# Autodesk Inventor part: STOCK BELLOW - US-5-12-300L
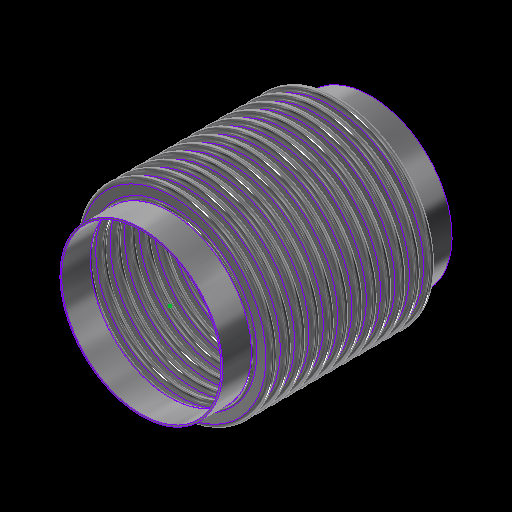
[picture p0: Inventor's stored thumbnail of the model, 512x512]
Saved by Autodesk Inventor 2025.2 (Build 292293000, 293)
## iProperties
Category: 22 GA (0.030 THICK)
RuleStatus: InUse
Created: 2024-01
Part Number: STOCK BELLOW - US-5-12-300L
Project: =STOCK BELLOWS: <Stock Number><SFILL>
Material: ASTM A240-304
Description: =STOCK BELLOWS: <Stock Number>, <SID_> I.D., <SOD_> O.D., <SPLY_> PLY, <Category>, <SNET_CONS> CONS.<PITCH_><STANGENT_> TANGENT<SFILL>
Document SubType Name: Sheet Metal
Designer: GS
Stock Number: U.S-5-12-300L
Surface Area: 4755.04 cm^2
Volume: 359.21 cm^3
Sheet Metal Rule: Default
Appearance: STAINLESS STEEL
Mass: 2894.25 g
Density: 8.05729 g/cm^3
THK: 0.036
ID: 3.500
OD: 4.250
CONS_: 2
PITCH: 0.500
TANGENT: 0.500
BELLOWS_UPSET: 0.000
d79: 1.000
d82: 1.000
d83: 26.000
d84: 24.000
d174: 8
d214: 8
STHK_: 0.030
SID_: 5.560
SOD_: 6.810
SPITCH_: 0.500
STANGENT__: 1.000
SBELLOWS_UPSET_: 0.000
SDIFF_TAN: 1.000
d252: 2
d275: 2
d287: 0.050
d289: 0.500
d290: 0.000
SOD_NECK: 5 11/16
PLY: 1
PSET: 4.178
PBAR: 1.035
COUNTER: 1.500
NET_TUBE: 3.071
CONS: 2
S_CONS: 0
NET_CONS: 2
ID_M: 88.90 mm
OD_M: 107.95 mm
THK_M: 0.91 mm
ID_U: 3.500 in
OD_U: 4.250 in
THK_U: 0.036 in
TANGENT2: 0.500
TAN_TO_TAN: 1.000 in
d80: 2.571
d81: 10
SID: 2.375
SCONS_: 12
SPITCH: 0.250
STANGENT_: 1.000
SBELLOWS_UPSET: 0.000
SNET_CONS: 12
SS_CONS: 0
SCONS: 8
d190: 8
d191: 1
d192: 1
d193: 8
d194: 0
SIZE: 5.00
PRESSURE: 300
d230: 8
STANGENT: 4.000
SPLY_: 2
d233: 8
d234: 0
d263: 2
d265: 1
d268: 2
d269: 0
d286: 2
d288: 1
d291: 2
d292: 0
SREROLL: 0.750
BLETP: 1.000 ul
PRES_Copy: 85
MATTABLE: 20 GA (0.036 THICK)
PART_NUMBER: U.S-5-12-300L
PITCH_: =, <SPITCH_> PITCH,
CFILL: .
SFILL: .
MESH: ,
COMP: 1.11
EXT: 0.56
LAT: 0.36
ANG: 573
ASR: 2144
LSR: 3418
ANSR: 179
PRES: 300
COMPM: 11.1
EXTM: 5.55
LATM: 3.60
ASRM: 375.479
PRESM: 20.684
LSRM: 598.594
ANSRM: 31.348
TEMPMIN: 20
TEMPMAX: 800
TEMPMINM: -7
TEMPMAXM: 427
WEIGHTM: 2.894
WEIGHT: 6.381
Author: GS
Keywords: 20 GA (0.036 THICK)
Comments: =STOCK BELLOW - <STOCK NUMBER>
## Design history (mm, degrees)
sketch "Sketch2"
  geometry: L1 (0, -177.245)-(0, 562.856) reference; L2 (45.364, 0)-(44.45, 0); L3 (48.082, -2.718)-(50.343, -2.718); L4 (48.082, -3.632)-(50.343, -3.632); L5 (50.343, -9.982)-(48.082, -9.982); L6 (50.343, -9.068)-(48.082, -9.068); L7 (45.364, -12.7)-(44.45, -12.7); L8 (48.082, 0)-(48.082, -12.7); L9 (50.343, -6.35)-(53.975, -6.35); L10 (44.45, 0)-(44.45, -12.7); L11 (20.376, 102.841)-(20.376, 101.926); L12 (58.262, 457.127)-(58.262, 349.177); L13 (58.262, 444.427)-(58.262, 336.477); L14 (93.133, -58.817)-(93.133, -71.517); L15 (118.746, -66.401)-(118.746, -66.401); L16 (50.343, -9.068)-(50.343, -9.982); L17 (48.082, -9.068)-(48.082, -9.982); L18 (48.082, -9.525)-(50.343, -9.525); L19 (53.975, 0)-(53.975, -12.7); L20 (-50.343, -9.068)-(-50.343, -9.982); L21 (-50.343, -2.718)-(-48.082, -2.718); L22 (-50.343, -3.632)-(-48.082, -3.632); L23 (-48.082, -9.068)-(-50.343, -9.068); L24 (-50.343, -9.525)-(-48.082, -9.525); L25 (-48.082, -9.982)-(-50.343, -9.982); L26 (-48.082, -9.068)-(-48.082, -9.982); L27 (-44.45, 0.653)-(-44.45, -12.047); L28 (-48.082, -6.35)-(-44.45, -6.35); L29 (-50.343, 0.653)-(-50.343, -12.7); L30 (-53.061, 0)-(-53.975, 0); L31 (-53.975, 0)-(-53.975, -12.7); L32 (-53.061, -12.7)-(-53.975, -12.7); A1 r 2.718 centre (48.082, 0) between (45.364, 0) and (48.082, -2.718); A2 r 3.632 centre (48.082, 0) between (44.45, 0) and (48.082, -3.632); A3 r 3.632 centre (50.343, -6.35) between (50.343, -9.982) and (50.343, -2.718); A4 r 2.718 centre (50.343, -6.35) between (50.343, -9.068) and (50.343, -3.632); A5 r 2.718 centre (48.082, -12.7) between (48.082, -9.982) and (45.364, -12.7); A6 r 3.632 centre (48.082, -12.7) between (48.082, -9.068) and (44.45, -12.7); A7 r 3.175 centre (50.343, -6.35) between (50.343, -9.525) and (53.518, -6.35); A8 r 3.175 centre (48.082, -12.7) between (48.082, -9.525) and (44.907, -12.7); A9 r 2.718 centre (-50.343, -12.7) between (-50.343, -9.982) and (-53.061, -12.7); A10 r 2.718 centre (-48.082, -6.35) between (-48.082, -9.068) and (-48.082, -3.632); A11 r 3.175 centre (-48.082, -6.35) between (-48.082, -9.525) and (-44.907, -6.35); A12 r 3.632 centre (-48.082, -6.35) between (-48.082, -9.982) and (-48.082, -2.718); A13 r 3.175 centre (-50.343, -12.7) between (-50.343, -9.525) and (-53.518, -12.7); A14 r 3.632 centre (-50.343, -12.7) between (-50.343, -9.068) and (-53.975, -12.7); A15 r 2.718 centre (-50.343, 0) between (-53.061, 0) and (-50.343, -2.718); A16 r 3.632 centre (-50.343, 0) between (-53.975, 0) and (-50.343, -3.632); 10 further points
  constraints: 62 end point, 38 point on circle, 20 tangent, 16 centre point, 12 parallel, 9 midpoint, 7 vertical, 6 coincident, 6 concentric, 6 point on line, 4 equal radius, 4 perpendicular, 3 horizontal, 1 collinear, 1 horizontal alignment, 10 other
  dimensions: "THK" = 0.9144 distance of L11.start L11.end; "ID" = 88.9 distance of L11.end point (20.376, 13.026); "OD" = 107.95 distance of L12.start L12.end; "PITCH" = 12.7 distance of L12.start L13.start; "TANGENT" = 12.7 distance of L14.start L14.end; "BELLOWS_UPSET" = 0 distance of L15.start L15.end; "d43" = 88.9 diameter of L10 L1 (= ID); "d44" = 107.95 diameter of L9.end L1 (= OD); "d45" = 0.9144 distance between parallel lines of L5 L6 (computed from THK, PLY); "d46" = 3.6322 radius of A3 (computed from PITCH, THK, PLY); "UPSET_PITCH" = 12.7 distance of L2.end L7.end (derived); "SIDEWALL_ANGLE" = 360 deg dimension on L3 L9 (derived); "CON_GAP" = 5.4356 distance of point (48.082, -9.068) point (48.082, -3.632) (derived); "TAN1" = 4.98728 dimension on A8 (derived); "TAN2" = 4.98728 dimension on A7 (derived); "LEG1" = 2.2606 distance of L18.start L18.end (derived); "d278" = 0.9144 distance between parallel lines of L25 L23 (derived); "d279" = 3.6322 radius of A12 (derived); "d280" = 12.7 distance of L30.end L31.end (derived); "d281" = 360 deg dimension on L21 L28 (derived); "d282" = 5.4356 distance of point (-50.343, -9.068) point (-50.343, -3.632) (derived); "d283" = 4.98728 dimension on A13 (derived); "d284" = 4.98728 dimension on A11 (derived); "d285" = 2.2606 distance of L24.start L24.end (derived); "d293" = 88.9 diameter of L27 L1 (derived); "d294" = 107.95 diameter of L31 L1 (derived)
  node "Sketch Rectangular Pattern1" dims "d31" = 25.4, "ID" = 88.9
  node "Sketch Rectangular Pattern2" dims "d39" = 25.4, "PITCH" = 12.7
revolve "CONS" stored, may be unused: angle "d48" = 90 deg
node "BELLOW MIDPLANE"
pattern_linear "Rectangular Pattern2" dims "d52" = 12.7 (= UPSET_PITCH)
sketch "Sketch5"
  geometry: C1 r 45.364 at (0, 0) reference; C2 r 44.45 at (0, 0) reference
extrude "TANGENT" new body sketch "Sketch5" distance "d53" = 12.7 (= TANGENT); taper "d54" = 0 deg
revolve "SAMETAN" stored, may be unused: angle "d65" = 90 deg
revolve "DIFFTAN" stored, may be unused: angle "d70" = 90 deg
sketch "Sketch9"
  geometry: L1 (53.319, 0)-(-53.319, 0) reference; L2 (0, -17.78)-(0, 17.78) reference; L3 (38.085, 0)-(-38.085, 0); L4 (38.085, -11.906)-(38.085, 11.906); L5 (25.385, -11.906)-(25.385, 11.906); L6 (13.15, 11.906)-(13.15, -11.906); L7 (-25.385, -11.906)-(-25.385, 11.906); L8 (-38.085, -11.906)-(-38.085, 11.906); L9 (37.291, -11.906)-(37.291, 11.906); L10 (38.085, -11.906)-(37.291, -11.906); L11 (38.085, 11.906)-(37.291, 11.906); L12 (13.546, 11.906)-(12.753, 11.906); L13 (12.753, 11.906)-(12.753, -11.906); L14 (12.753, -11.906)-(13.546, -11.906); L15 (13.546, -11.906)-(13.546, 11.906); L16 (-13.546, 11.906)-(-13.546, -11.906); L17 (-13.15, 11.906)-(-13.15, -11.906); L18 (-13.546, -11.906)-(-12.753, -11.906); L19 (-12.753, -11.906)-(-12.753, 11.906); L20 (-12.753, 11.906)-(-13.546, 11.906); L21 (-38.085, -11.906)-(-37.291, -11.906); L22 (-37.291, -11.906)-(-37.291, 11.906); L23 (-37.291, 11.906)-(-38.085, 11.906); L24 (-38.085, 11.906)-(-38.085, -11.906); L25 (38.085, -0.397)-(-38.085, -0.397); L26 (-38.085, -0.397)-(-38.085, 0.397); L27 (-38.085, 0.397)-(38.085, 0.397); L28 (38.085, 0.397)-(38.085, -0.397); L29 (-38.085, 11.906)-(38.085, 11.906); L30 (38.085, 11.906)-(38.085, 12.7); L31 (38.085, 12.7)-(-38.085, 12.7); L32 (-38.085, 12.7)-(-38.085, 11.906); L33 (38.085, -11.906)-(-38.085, -11.906); L34 (-38.085, -11.906)-(-38.085, -12.7); L35 (-38.085, -12.7)-(38.085, -12.7); L36 (38.085, -12.7)-(38.085, -11.906); 30 further points
  constraints: 68 end point, 13 midpoint, 13 parallel, 8 horizontal, 7 perpendicular, 6 equal length, 3 point on line, 2 vertical, 14 other
  dimensions: "d115" = 23.8125 distance of L4.start L4.end (derived); "d116" = 12.7 distance between parallel lines of L4 L5 (derived); "d117" = 12.23516 distance between parallel lines of L5 L6 (derived); "d125" = 38.53427 distance between parallel lines of L7 L6 (derived); "d127" = 12.7 distance between parallel lines of L8 L7 (derived); "d128" = 24.93516 distance between parallel lines of L6 L4 (derived); "d130" = 76.16943 distance between parallel lines of L8 L4 (derived); "RULER_THK" = 0.79375 distance between parallel lines of L4 L9; "d135" = 0.79375 distance of L13.end L14.end (derived); "d138" = 26.29911 distance of L13.end L16.end (derived); "d143" = 0.79375 distance of L22.end L8.end (derived); "d144" = 0.79375 distance between parallel lines of L27 L25 (derived)
extrude "RULER" join sketch "Sketch9" distance "d149" = 0.79375 (derived); taper "d150" = 0 deg
extrude "BARS" join sketch "Sketch9" distance "d151" = 0.79375 (derived); taper "d152" = 0 deg
pattern_linear "Rectangular Pattern4" dims "d155" = 26.29911 (derived)
sketch "Sketch13"
  geometry: L1 (93.149, -52.467)-(93.149, -77.867); L2 (72.136, 0)-(70.612, 0); L3 (72.136, -12.7)-(70.612, -12.7); L4 (82.55, -10.287)-(74.549, -10.287); L5 (82.55, -8.763)-(74.549, -8.763); L6 (82.55, -6.35)-(86.487, -6.35); L7 (74.549, -2.413)-(82.55, -2.413); L8 (74.549, 0)-(74.549, -12.7); L9 (70.612, 0)-(70.612, -12.7); L10 (58.254, -323.457)-(58.254, -496.431); L11 (58.254, -336.157)-(58.254, -509.131); L12 (58.254, -361.557)-(58.254, -534.531); L13 (58.254, -374.257)-(58.254, -547.231); L14 (58.254, -386.957)-(58.254, -559.931); L15 (58.254, -399.657)-(58.254, -572.631); L16 (58.254, -412.357)-(58.254, -585.331); L17 (58.254, -348.857)-(58.254, -521.831); L18 (20.376, 102.688)-(20.376, 101.926); L19 (74.549, -3.937)-(82.55, -3.937); L20 (0, -722.935)-(0, 240.292) reference; L21 (-23.752, 0)-(142.514, 0) reference; A1 r 2.413 centre (74.549, 0) between (72.136, 0) and (74.549, -2.413); A2 r 2.413 centre (74.549, -12.7) between (74.549, -10.287) and (72.136, -12.7); A3 r 3.937 centre (74.549, -12.7) between (74.549, -8.763) and (70.612, -12.7); A4 r 2.413 centre (82.55, -6.35) between (82.55, -8.763) and (82.55, -3.937); A5 r 3.937 centre (82.55, -6.35) between (82.55, -10.287) and (82.55, -2.413); A6 r 3.937 centre (74.549, 0) between (70.612, 0) and (74.549, -3.937); 6 further points; 1 other entity
  constraints: 38 end point, 15 point on circle, 9 tangent, 6 centre point, 6 parallel, 5 vertical alignment, 4 point on line, 4 vertical, 3 coincident, 3 concentric, 2 collinear, 2 equal radius, 1 horizontal, 1 perpendicular, 23 other
  dimensions: "SBELLOWS_UPSET_" = 0 distance of point (118.762, -66.401) point (118.762, -66.401); "STOTAL_THK_BELLOW__" = 1.524 distance between parallel lines of L4 L5 (derived); "d224" = 3.937 radius of A5 (derived); "d225" = 12.7 distance of L2.end L3.end (derived); "SSIDEWALL_ANGLE_" = 360 deg dimension on L7 L6 (derived); "SSCON_GAP_" = 4.826 distance of point (74.549, -8.763) point (74.549, -3.937) (derived); "d235" = 141.224 diameter of L9 L20 (derived); "d236" = 172.974 diameter of L6.end L20 (derived)
  node "Sketch Rectangular Pattern4" dims "d228" = 25.4
  node "Sketch Rectangular Pattern5" dims "d229" = 25.4
revolve "SBELLOW" stored, may be unused: angle "d197" = 90 deg
pattern_linear "Rectangular Pattern5" dims "d204" = 12.7 (derived)
revolve "STANGENT" stored, may be unused: angle "d240" = 90 deg
revolve "SSAMETAN" stored, may be unused: angle "d241" = 90 deg
revolve "SDIFFTAN" stored, may be unused: angle "d246" = 90 deg
revolve "INVCON" stored, may be unused: angle "d295" = 90 deg
pattern_linear "Rectangular Pattern6" dims "d298" = 12.7 (derived)
revolve "INVTANGENT" stored, may be unused: angle "d302" = 90 deg
revolve "INVSAMETAN" stored, may be unused: angle "d307" = 90 deg
revolve "INVDIFFTAN" stored, may be unused: angle "d312" = 90 deg
sketch "ID BELLOW MOUNT CALC"
  geometry: L1 (44.45, 0)-(38.1, 0); L2 (38.1, 0)-(38.1, 12.7); L3 (38.1, 12.7)-(44.45, 12.7); L4 (44.45, 12.7)-(44.45, 0); L5 (36.513, 12.7)-(35.598, 12.7); L6 (35.598, 12.7)-(35.598, 0); L7 (35.598, 0)-(36.513, 0); L8 (36.513, 0)-(36.513, 12.7); L9 (0, -2.54)-(0, 15.24) reference; L10 (-8.89, 0)-(53.34, 0) reference; 1 further point
  constraints: 16 end point, 5 parallel, 2 collinear, 2 horizontal, 2 perpendicular
  dimensions: "d314" = 12.7 distance of L5.end L6.end (derived); "d315" = 0.9144 distance of L5.start L5.end (derived); "IG" = 1.5875 distance between parallel lines of L2 L8; "PIPE_OD" = 88.9 diameter of L4 L9; "PIPE_WALL" = 6.35 distance of L2.end L3.end; "ID_MT_BELLOW" = 71.1962 diameter of L6 L9 (derived)
revolve "CFILL" stored, may be unused: angle "d320" = 90 deg
pattern_linear "Rectangular Pattern7" dims "d323" = 12.7 (derived)
revolve "SFILL" stored, may be unused: angle "d324" = 90 deg
pattern_linear "Rectangular Pattern8" dims "d327" = 12.7 (derived)
node "STOCK BELLOW MIDPLANE"
node "BELLOW"
sketch "Sketch6"
  geometry: L1 (-12.7, 45.364)-(0, 45.364); L2 (0, 45.364)-(0, 44.45); L3 (0, 44.45)-(-12.7, 44.45); L4 (-12.7, 44.45)-(-12.7, 45.364); L5 (10.16, 0)-(-60.96, 0) reference; L6 (-38.1, -89.422)-(-38.1, 153.44) reference; 1 further point
  constraints: 8 end point, 2 parallel, 1 horizontal, 1 perpendicular
  dimensions: "d61" = 12.7 distance of L2.end L3.end (derived); "d62" = 0.9144 distance of L1.end L2.end (derived); "d63" = 88.9 diameter of L3 L5 (derived); "d64" = 25.4 distance between parallel lines of L4 L6 (derived)
sketch "Sketch12"
  geometry: 1 further point
sketch "Sketch14"
  geometry: L1 (-25.4, 72.136)-(0, 72.136); L2 (0, 72.136)-(0, 70.612); L3 (0, 70.612)-(-25.4, 70.612); L4 (-25.4, 70.612)-(-25.4, 72.136); L5 (5.08, 0)-(-30.48, 0) reference; L6 (0, -14.427)-(0, 86.563) reference; 1 further point
  constraints: 8 end point, 2 parallel, 1 collinear, 1 horizontal, 1 perpendicular
  dimensions: "d237" = 1.524 distance of L3.end L1.start (derived); "d238" = 141.224 diameter of L3 L5 (derived); "d239" = 25.4 distance of L1.start L1.end (derived); "SOD_NECK" = 144.272 diameter of L1 L5 (derived)
sketch "Sketch15"
  geometry: L1 (-14.427, 0)-(86.563, 0) reference; L2 (70.612, -152.4)-(72.136, -152.4); L3 (72.136, -152.4)-(72.136, -177.8); L4 (72.136, -177.8)-(70.612, -177.8); L5 (70.612, -177.8)-(70.612, -152.4); L6 (0, -215.9)-(0, 50.8) reference; 1 further point
  constraints: 8 end point, 2 parallel, 1 horizontal, 1 perpendicular
  dimensions: "d205" = 25.4 distance of L4.end L2.start (derived); "d206" = 1.524 distance of L3.end L4.end (derived); "d207" = 141.224 diameter of L5 L6 (derived); "d208" = 152.4 distance between parallel lines of L1 L2 (derived)
node "TANGENT_"
node "SAME_TAN"
sketch "Sketch8"
  geometry: L1 (45.364, -25.4)-(44.45, -25.4); L2 (44.45, -25.4)-(44.45, -38.1); L3 (44.45, -38.1)-(45.364, -38.1); L4 (45.364, -38.1)-(45.364, -25.4); L5 (0, -48.26)-(0, 22.86) reference; L6 (-89.422, 0)-(153.44, 0) reference; 1 further point
  constraints: 8 end point, 2 parallel, 1 horizontal, 1 perpendicular
  dimensions: "d66" = 88.9 diameter of L2 L5 (derived); "TOTAL_THK_BELLOW" = 0.9144 distance of L2.end L3.end (derived); "d68" = 25.4 distance between parallel lines of L1 L6 (derived); "d69" = 12.7 distance of L1.end L2.end (derived)
node "DIFF_TAN"
node "Sketch Rectangular Pattern3" dims "d138" = 26.29911 (derived), "d141" = 25.4
node "SBELLOW_"
node "STANGENT_"
node "SSAME_TAN"
sketch "Sketch16"
  geometry: L1 (72.136, -152.4)-(70.612, -152.4); L2 (70.612, -152.4)-(70.612, -177.8); L3 (70.612, -177.8)-(72.136, -177.8); L4 (72.136, -177.8)-(72.136, -152.4); L5 (0, -215.9)-(0, 50.8) reference; L6 (-14.427, 0)-(86.563, 0) reference; 1 further point
  constraints: 8 end point, 2 parallel, 1 horizontal, 1 perpendicular
  dimensions: "SDIFF_TAN" = 25.4 distance of L3.end L1.start; "d243" = 1.524 distance of L2.end L3.end (derived); "d244" = 152.4 distance between parallel lines of L1 L6 (derived); "d245" = 141.224 diameter of L2 L5 (derived)
node "SDIFF_TAN"
body "Solid15"
sketch "Sketch17"
  geometry: L1 (53.975, 12.7)-(53.061, 12.7); L2 (53.061, 12.7)-(53.061, 0); L3 (53.061, 0)-(53.975, 0); L4 (53.975, 0)-(53.975, 12.7); L5 (0, -2.54)-(0, 15.24) reference; L6 (-10.795, 0)-(64.77, 0) reference; 2 further points
  constraints: 8 end point, 2 parallel, 1 horizontal, 1 midpoint, 1 perpendicular, 1 point on line
  dimensions: "INVTANGENT" = 12.7 distance of L3.end L1.start (derived); "d300" = 0.9144 distance of L1.start L1.end (derived); "d301" = 107.95 diameter of L4 L5 (derived)
body "Solid16"
sketch "Sketch18"
  geometry: L1 (53.975, -25.4)-(53.061, -25.4); L2 (53.061, -25.4)-(53.061, -38.1); L3 (53.061, -38.1)-(53.975, -38.1); L4 (53.975, -38.1)-(53.975, -25.4); L5 (-10.795, 0)-(64.77, 0) reference; L6 (0, -48.26)-(0, 22.86) reference; 1 further point
  constraints: 8 end point, 2 parallel, 1 horizontal, 1 perpendicular
  dimensions: "d303" = 25.4 distance between parallel lines of L1 L5 (derived); "d304" = 12.7 distance of L3.end L1.start (derived); "d305" = 0.9144 distance of L2.end L3.end (derived); "d306" = 107.95 diameter of L4 L6 (derived)
body "Solid17"
sketch "Sketch19"
  geometry: L1 (53.975, -25.4)-(53.061, -25.4); L2 (53.061, -25.4)-(53.061, -38.1); L3 (53.061, -38.1)-(53.975, -38.1); L4 (53.975, -38.1)-(53.975, -25.4); L5 (0, -48.26)-(0, 22.86) reference; L6 (-10.795, 0)-(64.77, 0) reference; 1 further point
  constraints: 8 end point, 2 parallel, 1 horizontal, 1 perpendicular
  dimensions: "d308" = 12.7 distance of L1.end L2.end (derived); "d309" = 107.95 diameter of L4 L5 (derived); "d310" = 0.9144 distance of L2.end L3.end (derived); "d311" = 25.4 distance between parallel lines of L1 L6 (derived)
body "Solid18"
body "Solid19"
body "Solid20"
other parameters: "BMPL" = -76.2, "PSET" = 106.1212 (computed from OD, THK, PLY) [user parameter], "PBAR" = 26.29911 (= 0.570796 x PITCH + OD - ID) [user parameter; used in 1 equation term], "COUNTER" = 15 [user parameter], "NET_TUBE" = 77.99823 (computed from CONS_, PBAR, TANGENT) [user parameter], "S_CONS" = 0 [user parameter; used in 1 equation term], "ID_M" = 88.9 (= ID) [user parameter], "OD_M" = 107.95 (= OD) [user parameter], "THK_M" = 0.9144 (= THK) [user parameter], "ID_U" = 88.9 (= ID) [user parameter], "OD_U" = 107.95 (= OD) [user parameter], "THK_U" = 0.9144 (= THK) [user parameter], "D_UNITS" = 0 [user parameter], "TANGENT2" = 12.7 [user parameter], "TAN_TO_TAN" = 25.4 [user parameter], "OD_NECK" = 90.7288 [user parameter], "d79" = 25.4, "d80" = 65.29823 [user parameter], "d82" = 25.4, "d83" = 660.4, "d84" = 609.6, "sa_0" = 4, "FRAME_THK" = 0.79375 [user parameter], "CON_FLAT" = 12.23516 [user parameter], "SID" = 60.325 [user parameter], "SPITCH" = 6.35 [user parameter], "STANGENT_" = 25.4 [user parameter], "SBELLOWS_UPSET" = 0 [user parameter], "SS_CONS" = 0 [user parameter], "STAN_TO_TAN_" = 152.4 [user parameter], "d100" = 1.524 [user parameter], "d191" = 25.4 [user parameter], "d194" = 0 [user parameter], "STANGENT" = 101.6 [user parameter], "d234" = 0 [user parameter], "SUPSET_PITCH_" = 12.7 [user parameter], "d269" = 0 [user parameter], "d287" = 1.27, "d289" = 12.7, "d290" = 0, "d292" = 0 [user parameter], "Thickness" = 3.048 (derived), "KFactor" = 4.4, "BendRadius" = 3.048 (derived), "BendReliefWidth" = 3.048 (derived), "BendReliefDepth" = 1.524 (derived), "CornerReliefSize" = 12.192 (derived), "SeamGap" = 0.00508, "MinimumRemnant" = 6.096 (derived), "TransitionRadius" = 3.048 (derived), "JacobiRadiusSize" = 3.048 (derived), "GapSize" = 3.048 (derived), "SREROLL" = 19.05 [user parameter], "CUR_STK_PITCH" = 12.7 [user parameter], "d328" = -76.2 (derived), "ASR" = 21440 [user parameter], "LSR" = 34180 [user parameter], "BLETP" = 1 [user parameter], "ASRM" = 3754.7872 [user parameter], "PRESM" = 206.83949 [user parameter], "LSRM" = 5985.9434 [user parameter], "ANSRM" = 313.4827 [user parameter], "TEMPMIN" = 2664.83333 [user parameter], "TEMPMAX" = 6998.16667 [user parameter], "TEMPMINM" = 2664.83333 [user parameter], "TEMPMAXM" = 6998.16667 [user parameter], "WEIGHT" = 28.94254 [user parameter], "WEIGHTM" = 0.02894 [user parameter]
